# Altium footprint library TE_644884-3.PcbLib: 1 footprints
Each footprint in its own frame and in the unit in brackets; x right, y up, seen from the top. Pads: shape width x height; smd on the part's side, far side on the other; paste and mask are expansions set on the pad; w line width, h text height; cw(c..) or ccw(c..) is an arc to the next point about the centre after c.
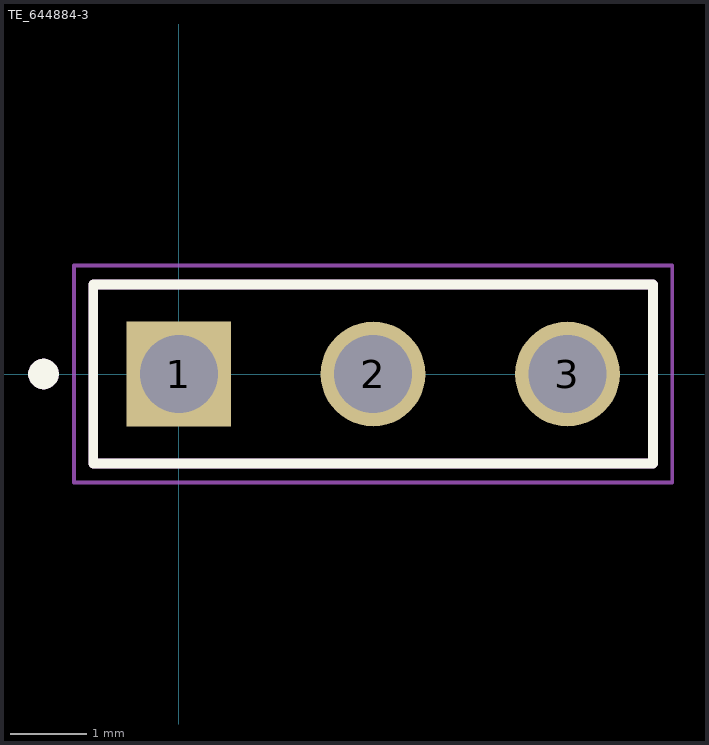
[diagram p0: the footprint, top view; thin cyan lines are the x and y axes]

## TE_644884-3 [mm]
pads (3):
  rect 1.37x1.37 / inner round 1.37 / far side rect 1.37x1.37 hole 1.02 mask+0.102: 1(0,0)
  round 1.37 hole 1.02 mask+0.102: 2(2.54,0) 3(5.08,0)
Top Overlay:
  circle w0.2: c-1.77,0 r0.1
  lines w0.127: -1.12,-1.17 -1.12,1.17 6.2,1.17 6.2,-1.17 -1.12,-1.17
Assembly Top:
  circle w0.2: c-1.77,0 r0.1
  lines w0.127: -1.12,-1.17 -1.12,1.17 6.2,1.17 6.2,-1.17 ; -1.12,-1.17 6.2,-1.17 ; -1.12,-1.17 6.2,-1.17
Courtyard Top:
  lines w0.05: -1.37,-1.42 -1.37,1.42 6.45,1.42 6.45,-1.42 -1.37,-1.42
3D body "step_temp.STEP": height 10.03, standoff -2.79, extent -1.118,-1.168 6.198,1.168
